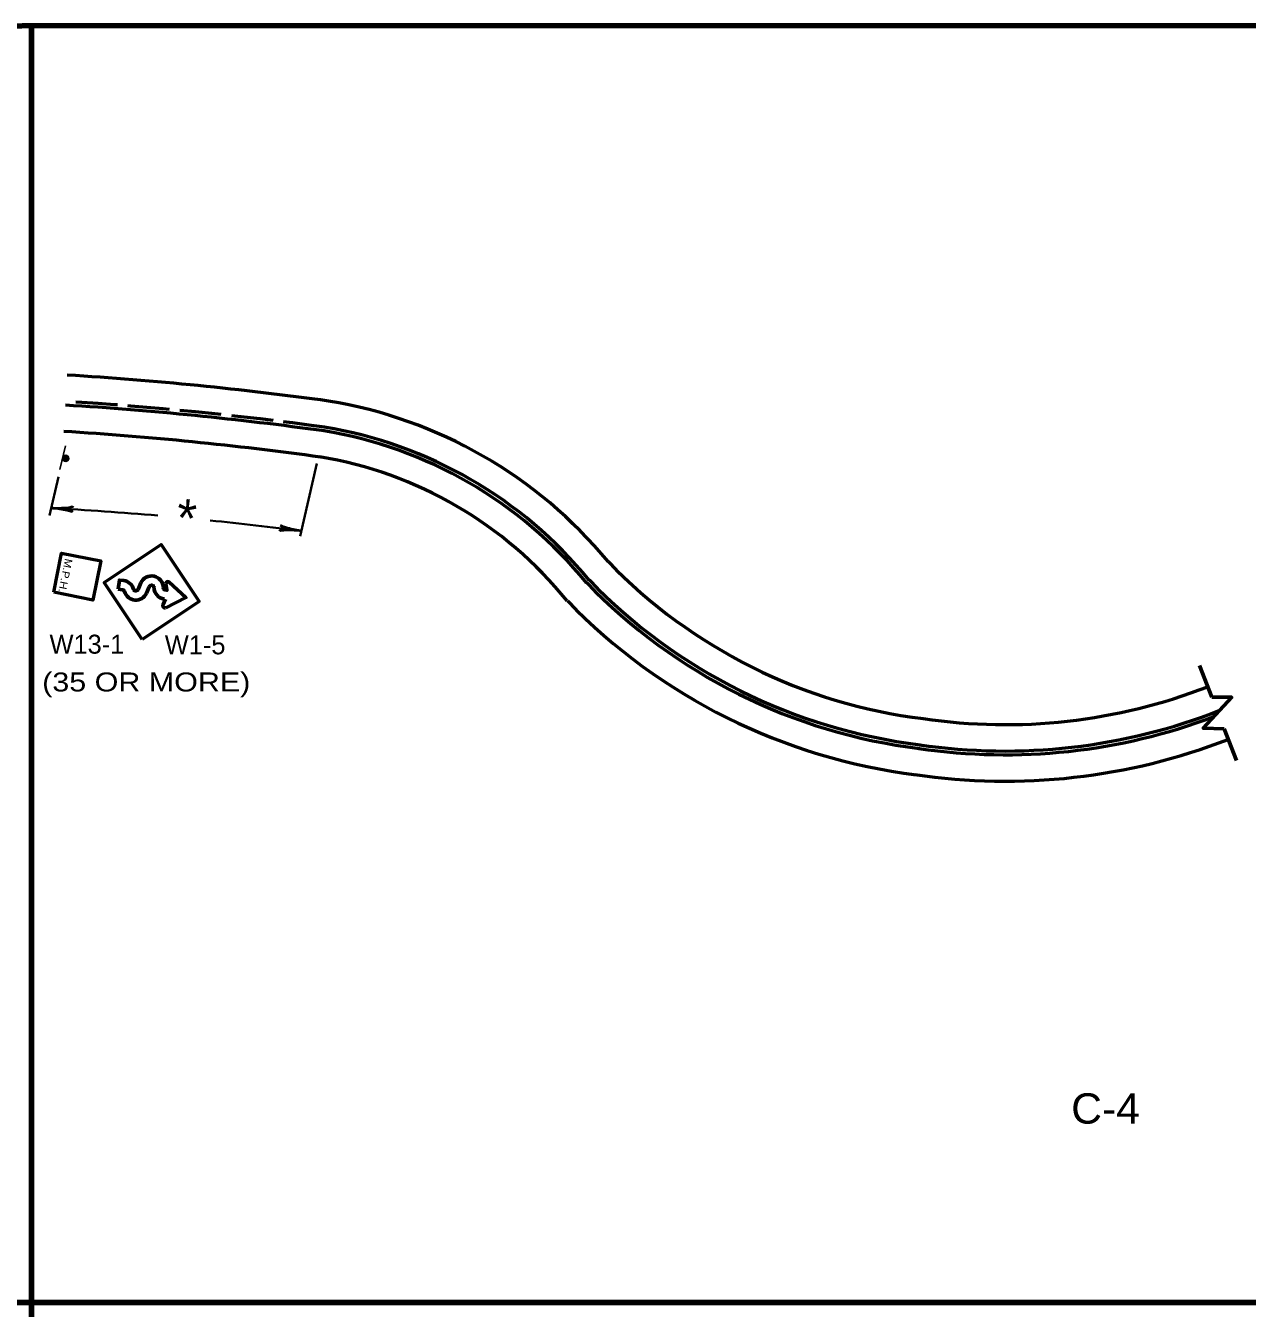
# Model space of a CAD drawing. Extents: x 522 to 1378, y -343 to 201.
# Drawn here: x 975.7 to 1168.8, y -8.5 to 194.3 of the extents above; entities that cross this region are included whole.
import ezdxf
from ezdxf.enums import TextEntityAlignment as Align

# ---------------------------------------------------------------- set-up
doc = ezdxf.new("R2010")
doc.units = 0
doc.header["$LTSCALE"] = 1.1
doc.linetypes.add('LONG_DASHED', pattern=[7.5, 6, -1.5])
for name, color, linetype, lineweight in [('1', 7, 'Continuous', 53), ('4', 7, 'Continuous', 25), ('61', 7, 'Continuous', 35)]:
    doc.layers.add(name, color=color, linetype=linetype, lineweight=lineweight)

msp = doc.modelspace()

# ---------------------------------------------------------------- hatches: boundary and pattern name
at = {"layer": '4'}
msp.add_hatch(color=256, dxfattribs=at).paths.add_polyline_path([(981.945, 125.384, 1), (982.169, 126.342, 1)])

# ---------------------------------------------------------------- linework, layer by layer
at = {"layer": '1', "lineweight": 35}
for p, q in [((1021.774, 125.072), (1019.136, 113.544)), ((980.904, 122.928), (979.51, 116.838))]:
    msp.add_line(p, q, dxfattribs=at)
at = {"layer": '1', "lineweight": 60}
for p, q in [((993.494, 105.15), (993.959, 106.175)), ((995.278, 105.578), (994.821, 104.542)), ((991.036, 105.099), (990.354, 105.193)), ((997.436, 102.676), (997.855, 103.586)), ((1161.26, 93.128), (1163.204, 88.123)), ((1165.158, 83.093), (1167.102, 78.088))]:
    msp.add_line(p, q, dxfattribs=at)
at = {"layer": '1', "lineweight": 158}
msp.add_lwpolyline([(1370.988, 194.26), (579.288, 194.16), (579.388, -331.84)], dxfattribs=at)
at = {"layer": '1'}
for points in [[(994.15, 97.248), (988.16, 106.235), (997.147, 112.225), (1003.137, 103.238)], [(980.182, 104.7), (981.418, 110.878), (987.596, 109.642), (986.36, 103.464)]]:
    msp.add_lwpolyline(points, close=True, dxfattribs=at)
at = {"layer": '1', "lineweight": 60}
for points in [[(990.354, 105.193), (990.553, 106.628), (991.237, 106.533)], [(997.817, 105.054), (998.055, 105.021), (997.9, 106.011)], [(998.424, 106.301), (1001.071, 103.866), (997.861, 102.244)], [(1163.204, 88.123), (1166.339, 88.105), (1161.855, 83.189), (1165.158, 83.093)]]:
    msp.add_lwpolyline(points, dxfattribs=at)
at = {"layer": '1'}
for centre, radius, start, end in [((948.22, -412.332), 552.411, 82.15692, 86.46117), ((948.22, -412.332), 547.646, 82.15692, 86.46117), ((1011.909, 63.409), 72.452, 39.5398, 80.71258), ((948.22, -412.332), 543.477, 82.15692, 86.46117), ((1011.909, 63.409), 67.687, 39.22241, 80.71258), ((1011.909, 63.409), 68.283, 39.26451, 80.71258), ((1011.909, 63.409), 63.517, 38.95034, 80.71258), ((1127.77, 167.571), 83.467, 224.05398, 262.99476), ((1127.77, 167.571), 88.232, 224.05398, 262.99476), ((1127.77, 167.571), 87.637, 224.05398, 262.99476), ((1127.77, 167.571), 92.402, 224.05398, 262.99476), ((1130.548, 172.187), 88.415, 261.57252, 291.22948), ((1130.548, 172.187), 92.584, 261.57252, 291.47901), ((1130.548, 172.187), 93.18, 261.57252, 290.74265), ((1130.548, 172.187), 97.35, 261.57252, 291.22948)]:
    msp.add_arc(centre, radius, start, end, dxfattribs=at)
at = {"layer": '1', "linetype": 'LONG_DASHED'}
msp.add_arc((948.22, -412.332), 548.242, 82.15692, 86.46117, dxfattribs=at)
at = {"layer": '1', "lineweight": 35}
for start, end in [(85.08879, 86.86654), (82.6785, 84.21221)]:
    msp.add_arc((950.071, -424.657), 543.477, start, end, dxfattribs=at)
at = {"layer": '1', "lineweight": 60}
for centre, radius, start, end in [((990.984, 104.71), 1.842, 15.58884, 82.0919), ((995.639, 105.425), 1.845, 0.49189, 155.85969), ((995.636, 105.415), 0.393, 0.18359, 155.64765), ((997.873, 105.44), 0.389, 179.98577, 262.17683), ((998.218, 106.058), 0.32, 50.18696, 188.80453), ((990.974, 104.702), 0.396, 14.34677, 80.81696), ((993.134, 105.3), 1.845, 195.69332, 335.88212), ((993.134, 105.309), 0.391, 195.57732, 335.59274), ((997.872, 105.44), 1.843, 180.73435, 262.30158), ((997.729, 102.54), 0.32, 155.37625, 293.99382)]:
    msp.add_arc(centre, radius, start, end, dxfattribs=at)
at = {"layer": '1', "lineweight": 40}
for centre, major_axis, ratio, start_param, end_param in [((981.107, 117.68), (-2.093, 0.326), 0.07063, 3.1407148, 5.41811), ((981.104, 118.267), (-2.15, -0.07), 0.122415, 0.8963533, 3.1415927), ((1017.989, 114.227), (2.149, -0.087), 0.122415, 0.8963533, 3.1415927), ((1018.028, 114.812), (2.064, -0.478), 0.07063, 3.1407148, 5.41811)]:
    msp.add_ellipse(centre, major_axis=major_axis, ratio=ratio, start_param=start_param, end_param=end_param, dxfattribs=at)
at = {"layer": '4'}
msp.add_line((982.028, 127.841), (981.151, 124.103), dxfattribs=at)
msp.add_circle((982.057, 125.863), 0.492, dxfattribs=at)
at = {"layer": '61', "lineweight": 158}
for p, q in [((976.669, 194.21), (976.686, -167.206)), ((1370.988, -7.57), (579.326, -7.57))]:
    msp.add_line(p, q, dxfattribs=at)

# ---------------------------------------------------------------- texts
at = {"layer": '1'}
msp.add_text('*', height=6, rotation=354.773, dxfattribs=at).set_placement((999.314, 113.572))
at = {"layer": '1', "width": 1.1}
msp.add_text('M.P.H.', height=1.2, rotation=258.499, dxfattribs=at).set_placement((981.967, 110.093))
at = {"layer": '1'}
for s, p in [('W13-1', (985.411, 94.987)), ('W1-5', (1002.518, 94.887))]:
    msp.add_text(s, height=3, dxfattribs=at).set_placement(p, align=Align.CENTER)
for s, height, width, p in [('(35 OR MORE)', 3, 1.2, (994.791, 89.015)), ('C-4', 4.8, 1.05, (1146.4, 20.699))]:
    msp.add_text(s, height=height, dxfattribs=dict(at, width=width)).set_placement(p, align=Align.CENTER)

doc.saveas('drawing.dxf')
